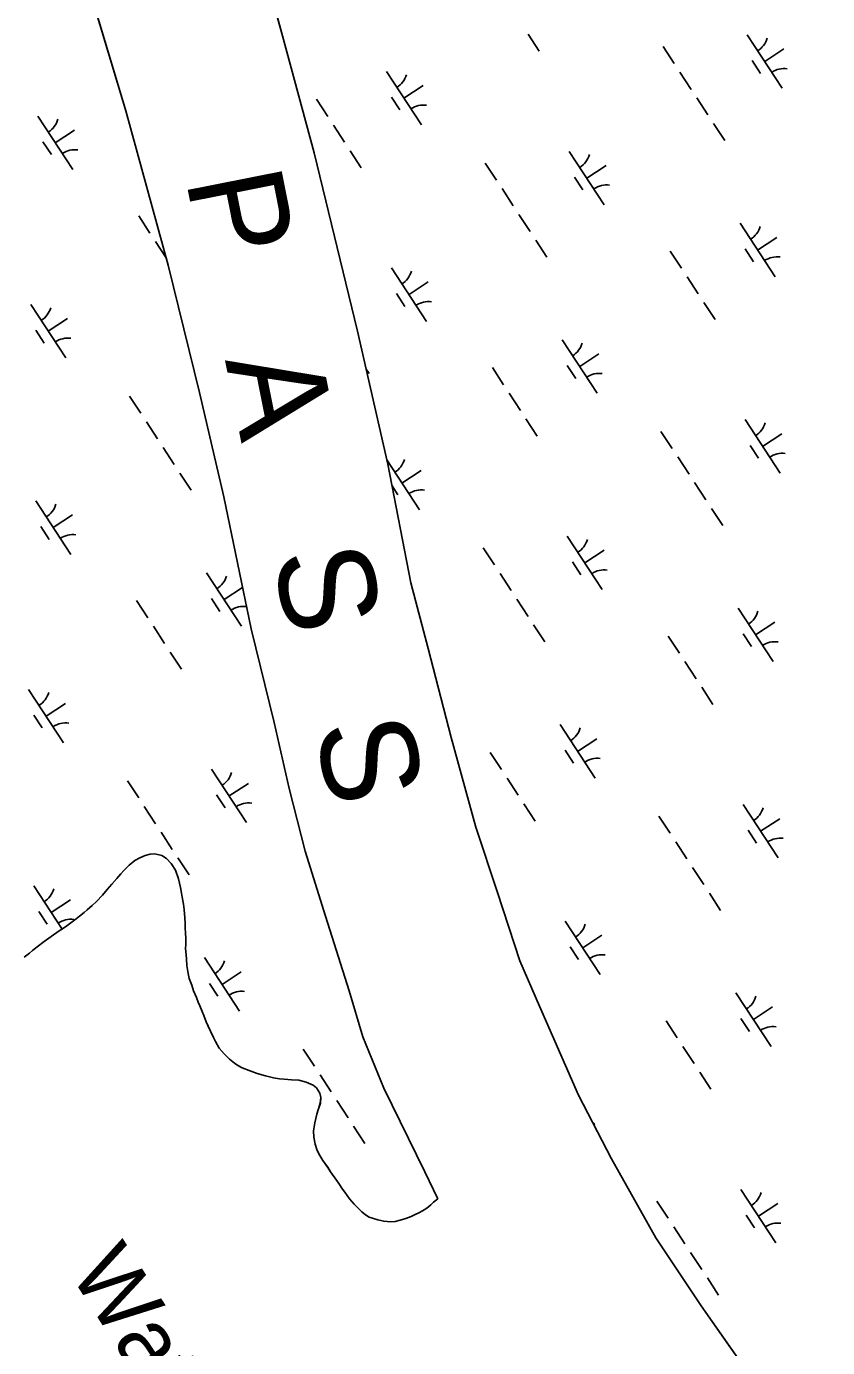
# Model space of a CAD drawing. Extents: x 3945642 to 3966284, y 206476 to 228921.
# Drawn here: x 3962719 to 3963346, y 213624 to 214658 of the extents above; entities that cross this region are included whole.
import ezdxf

# ---------------------------------------------------------------- set-up
doc = ezdxf.new("R2010")
doc.units = 0
for name, color, linetype in [('V-RIVR-IDEN', 7, 'Continuous'), ('V-TOPO-SHOR', 7, 'Continuous'), ('V-WETL-SWMP', 7, 'Continuous')]:
    doc.layers.add(name, color=color, linetype=linetype)

msp = doc.modelspace()

# ---------------------------------------------------------------- linework, layer by layer
at = {"layer": 'V-TOPO-SHOR'}
for points in [[(3962736.8, 215156.6), (3962773.4, 215081.9), (3962808.9, 215001.2), (3962834.9, 214934.8), (3962861.9, 214852.6), (3962884.9, 214776.1), (3962919.8, 214650.2), (3962944.5, 214558.8), (3962978.3, 214419.3), (3963002.1, 214315.1), (3963020.1, 214222.4), (3963033.6, 214171), (3963051.6, 214101.2), (3963070.9, 214031.3), (3963088, 213980), (3963105.5, 213926.7), (3963120.9, 213891.2), (3963151.2, 213821.4), (3963177.1, 213771.8), (3963211.9, 213710), (3963247.2, 213656.6), (3963292.5, 213592.3), (3963347.3, 213530.2)], [(3963041.3, 213740.5), (3963031.1, 213761.6), (3962999.1, 213827), (3962982.7, 213867.2), (3962971.8, 213903.2), (3962953.4, 213961.6), (3962937.5, 214012.5), (3962925, 214061.4), (3962913.2, 214113.1), (3962895.2, 214186.4), (3962873.9, 214289.6), (3962854.8, 214371.1), (3962830.3, 214470.9), (3962797.1, 214591.7), (3962767.6, 214690.2), (3962738.9, 214781.5), (3962714.1, 214844.4), (3962681.2, 214920), (3962656.7, 214977.6), (3962637, 215021), (3962616.5, 215070.2), (3962596.5, 215120.2)], [(3962717.6, 213929.4), (3962721.8, 213932.7), (3962724.2, 213934.8), (3962727.8, 213937.5), (3962733.3, 213941.7), (3962738.8, 213945.7), (3962745, 213950), (3962747.6, 213951.6), (3962751, 213954), (3962754.1, 213956.4), (3962758.4, 213959.5), (3962761, 213961.5), (3962764.5, 213964.5), (3962766.9, 213966.6), (3962770.7, 213969.9), (3962774.1, 213973.1), (3962778.8, 213977.9), (3962782.5, 213982.5), (3962786.2, 213986.7), (3962790.1, 213991.1), (3962793.3, 213994.6), (3962795.6, 213997.3), (3962799.8, 214001.4), (3962804.3, 214005), (3962808.2, 214007.2), (3962812.2, 214009), (3962816.3, 214010), (3962819.8, 214010.2), (3962825.3, 214009), (3962829.1, 214006.7), (3962832.7, 214002.8), (3962835.9, 213997.5), (3962838.4, 213990.8), (3962840, 213983.9), (3962840.8, 213979.6), (3962841.3, 213976.5), (3962842.2, 213970.9), (3962842.8, 213966.7), (3962843.4, 213960.2), (3962843.5, 213955.9), (3962843.6, 213952.8), (3962843.9, 213947.9), (3962844, 213944.5), (3962844.1, 213939.4), (3962843.9, 213936.2), (3962844.3, 213931.2), (3962844.5, 213927.9), (3962845, 213922.9), (3962845.5, 213919.7), (3962846, 213916.6), (3962846.8, 213912.7), (3962848.7, 213907.7), (3962850.2, 213903.1), (3962852.4, 213897.9), (3962853.8, 213894.3), (3962855, 213891.4), (3962857, 213886.9), (3962858.2, 213883.8), (3962860, 213879), (3962861.3, 213876), (3962863.3, 213871.6), (3962865.7, 213866.5), (3962867.3, 213863.4), (3962870.3, 213858.2), (3962874.2, 213853.8), (3962878.2, 213849.7), (3962882.2, 213846.6), (3962884.8, 213844.8), (3962888.2, 213842.9), (3962893.7, 213840.7), (3962900, 213838.5), (3962906.4, 213836.6), (3962912.8, 213835.2), (3962917.4, 213834.4), (3962920.9, 213834.1), (3962926.8, 213833.6), (3962932.6, 213833.2), (3962938.3, 213831.8), (3962943.7, 213829.3), (3962946.2, 213827.2), (3962949, 213823), (3962949.7, 213819.6), (3962949.3, 213815.2), (3962947.7, 213810.1), (3962946.6, 213806.7), (3962944.9, 213800), (3962943.9, 213793.6), (3962944.3, 213788.6), (3962945.2, 213783.3), (3962946.7, 213779.1), (3962948.1, 213775.7), (3962951.4, 213770.3), (3962955.1, 213765), (3962957.4, 213761.5), (3962962.1, 213755.1), (3962963.8, 213752.4), (3962966.7, 213748), (3962968.6, 213745.5), (3962972.1, 213740.3)], [(3962972.1, 213740.3), (3962975.7, 213736.3), (3962978.8, 213733), (3962981.9, 213730.2), (3962984.7, 213727.8), (3962987.6, 213726.1), (3962990.8, 213724.9), (3962994.2, 213723.9), (3962998.9, 213722.9), (3963004.1, 213722.5), (3963007.9, 213722.7), (3963011.8, 213723.8), (3963016.1, 213725), (3963020.5, 213726.7), (3963023.6, 213728.1), (3963026.5, 213729.5), (3963029.3, 213731), (3963032.7, 213733), (3963035.8, 213735.6), (3963037.9, 213737.8), (3963041.3, 213740.5)]]:
    msp.add_lwpolyline(points, dxfattribs=at)
at = {"layer": 'V-WETL-SWMP'}
for p, q in [((3962919.8, 214650.2), (3962884.9, 214776.1)), ((3962797.1, 214591.7), (3962767.6, 214690.2)), ((3962944.5, 214558.8), (3962919.8, 214650.2)), ((3963111.8, 214651.6), (3963120.6, 214638.2)), ((3963283.3, 214651), (3963310.7, 214609.2)), ((3963217.5, 214641.9), (3963226.2, 214628.5)), ((3963297, 214630.1), (3963312, 214640)), ((3963001, 214622.4), (3963028.4, 214580.6)), ((3963287.2, 214630.9), (3963293.8, 214620.9)), ((3963230.6, 214621.8), (3963239.4, 214608.4)), ((3963005, 214602.3), (3963011.6, 214592.3)), ((3963014.7, 214601.5), (3963029.8, 214611.4)), ((3963243.8, 214601.7), (3963252.5, 214588.4)), ((3962830.3, 214470.9), (3962797.1, 214591.7)), ((3962946.4, 214600.6), (3962955.1, 214587.2)), ((3962728.3, 214587.5), (3962755.7, 214545.7)), ((3963256.9, 214581.7), (3963265.7, 214568.3)), ((3962742, 214566.6), (3962757.1, 214576.4)), ((3962959.5, 214580.5), (3962968.3, 214567.1)), ((3962732.3, 214567.4), (3962738.9, 214557.3)), ((3962972.7, 214560.4), (3962981.4, 214547)), ((3963144.1, 214559.9), (3963171.5, 214518)), ((3962978.3, 214419.3), (3962944.5, 214558.8)), ((3963078.3, 214550.7), (3963087.1, 214537.4)), ((3963148.1, 214539.7), (3963154.7, 214529.7)), ((3963157.8, 214539), (3963172.9, 214548.8)), ((3963091.5, 214530.7), (3963100.2, 214517.3)), ((3962807.2, 214509.4), (3962816, 214496)), ((3963104.6, 214510.6), (3963113.4, 214497.2)), ((3963277.7, 214503.6), (3963305.1, 214461.8)), ((3962820.4, 214489.3), (3962828.7, 214476.6)), ((3963117.8, 214490.5), (3963126.5, 214477.1)), ((3963291.4, 214482.7), (3963306.5, 214492.6)), ((3963223, 214481.8), (3963231.8, 214468.4)), ((3963281.7, 214483.5), (3963288.2, 214473.5)), ((3962854.8, 214371.1), (3962830.3, 214470.9)), ((3963005, 214468.7), (3963032.4, 214426.9)), ((3963018.7, 214447.8), (3963033.7, 214457.7)), ((3963236.2, 214461.7), (3963244.9, 214448.3)), ((3963008.9, 214448.6), (3963015.5, 214438.6)), ((3962722.8, 214440.1), (3962750.2, 214398.3)), ((3963249.3, 214441.7), (3963258.1, 214428.3)), ((3962736.5, 214419.2), (3962751.5, 214429.1)), ((3962726.7, 214420), (3962733.3, 214409.9)), ((3963002.1, 214315.1), (3962978.3, 214419.3)), ((3963138.6, 214412.5), (3963166, 214370.7)), ((3963152.3, 214391.6), (3963167.3, 214401.4)), ((3962985.2, 214389.4), (3962987.4, 214386)), ((3963083.9, 214390.7), (3963092.6, 214377.3)), ((3963142.5, 214392.4), (3963149.1, 214382.3)), ((3962800, 214368.4), (3962808.8, 214355.1)), ((3962873.9, 214289.6), (3962854.8, 214371.1)), ((3963097, 214370.6), (3963105.8, 214357.2)), ((3962813.2, 214348.4), (3962822, 214335)), ((3963110.2, 214350.5), (3963118.9, 214337.1)), ((3963281.6, 214350), (3963309, 214308.1)), ((3963215.8, 214340.8), (3963224.6, 214327.4)), ((3963295.3, 214329), (3963310.4, 214338.9)), ((3962826.4, 214328.3), (3962835.1, 214314.9)), ((3963285.6, 214329.8), (3963292.2, 214319.8)), ((3963001.3, 214318.5), (3963026.8, 214279.5)), ((3963020.1, 214222.4), (3963002.1, 214315.1)), ((3963229, 214320.8), (3963237.8, 214307.4)), ((3962839.5, 214308.2), (3962848.3, 214294.8)), ((3963013.1, 214300.4), (3963028.2, 214310.3)), ((3963005.4, 214298.2), (3963010, 214291.2)), ((3963242.1, 214300.7), (3963250.9, 214287.3)), ((3962726.7, 214286.4), (3962754.1, 214244.6)), ((3962895.2, 214186.4), (3962873.9, 214289.6)), ((3962740.4, 214265.5), (3962755.5, 214275.4)), ((3963255.3, 214280.6), (3963264.1, 214267.2)), ((3962730.7, 214266.3), (3962737.2, 214256.3)), ((3963142.5, 214258.8), (3963169.9, 214217)), ((3963076.7, 214249.7), (3963085.5, 214236.3)), ((3963156.2, 214237.9), (3963171.3, 214247.8)), ((3962860.3, 214230.2), (3962887.7, 214188.4)), ((3963089.9, 214229.6), (3963098.6, 214216.2)), ((3963146.5, 214238.7), (3963153, 214228.6)), ((3962874, 214209.3), (3962888.5, 214218.8)), ((3963033.6, 214171), (3963020.1, 214222.4)), ((3962864.2, 214210.1), (3962870.8, 214200)), ((3963103, 214209.5), (3963111.8, 214196.1)), ((3962805.6, 214208.4), (3962814.4, 214195)), ((3963276.1, 214202.6), (3963303.5, 214160.7)), ((3962818.7, 214188.3), (3962827.5, 214174.9)), ((3963116.2, 214189.4), (3963124.9, 214176.1)), ((3963289.8, 214181.7), (3963304.8, 214191.5)), ((3962913.2, 214113.1), (3962895.2, 214186.4)), ((3963221.4, 214180.7), (3963230.2, 214167.4)), ((3963280, 214182.5), (3963286.6, 214172.4)), ((3962831.9, 214168.2), (3962840.7, 214154.8)), ((3963051.6, 214101.2), (3963033.6, 214171)), ((3963234.5, 214160.7), (3963243.3, 214147.3)), ((3962721.1, 214139), (3962748.5, 214097.2)), ((3963247.7, 214140.6), (3963256.5, 214127.2)), ((3962734.8, 214118.1), (3962749.9, 214128)), ((3962725.1, 214118.9), (3962731.7, 214108.9)), ((3962925, 214061.4), (3962913.2, 214113.1)), ((3963136.9, 214111.4), (3963164.3, 214069.6)), ((3963070.9, 214031.3), (3963051.6, 214101.2)), ((3963150.6, 214090.5), (3963165.7, 214100.4)), ((3963082.3, 214089.6), (3963091, 214076.2)), ((3963140.9, 214091.3), (3963147.5, 214081.3)), ((3962864.2, 214076.5), (3962891.6, 214034.7)), ((3962798.4, 214067.4), (3962807.2, 214054)), ((3962877.9, 214055.6), (3962893, 214065.4)), ((3963095.4, 214069.5), (3963104.2, 214056.1)), ((3962868.2, 214056.4), (3962874.8, 214046.3)), ((3962937.5, 214012.5), (3962925, 214061.4)), ((3962811.6, 214047.3), (3962820.3, 214033.9)), ((3963108.6, 214049.4), (3963117.3, 214036)), ((3963280, 214048.9), (3963307.4, 214007.1)), ((3963214.2, 214039.8), (3963223, 214026.4)), ((3963293.7, 214028), (3963308.8, 214037.8)), ((3962824.7, 214027.2), (3962833.5, 214013.8)), ((3963088, 213980), (3963070.9, 214031.3)), ((3963284, 214028.8), (3963290.6, 214018.7)), ((3962953.4, 213961.6), (3962937.5, 214012.5)), ((3963227.4, 214019.7), (3963236.1, 214006.3)), ((3962799.8, 214001.4), (3962804.3, 214005)), ((3962804.3, 214005), (3962808.2, 214007.2)), ((3962808.2, 214007.2), (3962812.2, 214009)), ((3962812.2, 214009), (3962816.3, 214010)), ((3962816.3, 214010), (3962819.8, 214010.2)), ((3962819.8, 214010.2), (3962825.3, 214009)), ((3962825.3, 214009), (3962829.1, 214006.7)), ((3962829.1, 214006.7), (3962832.7, 214002.8)), ((3962832.7, 214002.8), (3962835.9, 213997.5)), ((3962837.9, 214007.1), (3962846.7, 213993.8)), ((3962790.1, 213991.1), (3962793.3, 213994.6)), ((3962793.3, 213994.6), (3962795.6, 213997.3)), ((3962795.6, 213997.3), (3962799.8, 214001.4)), ((3962835.9, 213997.5), (3962838.4, 213990.8)), ((3963240.5, 213999.6), (3963249.3, 213986.2)), ((3962725.1, 213985.3), (3962747.3, 213951.4)), ((3962778.8, 213977.9), (3962782.5, 213982.5)), ((3962782.5, 213982.5), (3962786.2, 213986.7)), ((3962786.2, 213986.7), (3962790.1, 213991.1)), ((3962838.4, 213990.8), (3962840, 213983.9)), ((3962840, 213983.9), (3962840.8, 213979.6)), ((3962738.8, 213964.4), (3962753.8, 213974.3)), ((3962770.7, 213969.9), (3962774.1, 213973.1)), ((3962774.1, 213973.1), (3962778.8, 213977.9)), ((3962840.8, 213979.6), (3962841.3, 213976.5)), ((3962841.3, 213976.5), (3962842.2, 213970.9)), ((3962842.2, 213970.9), (3962842.8, 213966.7)), ((3963105.5, 213926.7), (3963088, 213980)), ((3963253.7, 213979.5), (3963262.4, 213966.1)), ((3962729, 213965.2), (3962735.6, 213955.2)), ((3962758.4, 213959.5), (3962761, 213961.5)), ((3962761, 213961.5), (3962764.5, 213964.5)), ((3962764.5, 213964.5), (3962766.9, 213966.6)), ((3962766.9, 213966.6), (3962770.7, 213969.9)), ((3962842.8, 213966.7), (3962843.4, 213960.2)), ((3962971.8, 213903.2), (3962953.4, 213961.6)), ((3962745, 213950), (3962747.6, 213951.6)), ((3962747.6, 213951.6), (3962751, 213954)), ((3962751, 213954), (3962754.1, 213956.4)), ((3962754.1, 213956.4), (3962758.4, 213959.5)), ((3962843.4, 213960.2), (3962843.5, 213955.9)), ((3962843.5, 213955.9), (3962843.6, 213952.8)), ((3962843.6, 213952.8), (3962843.9, 213947.9)), ((3963140.9, 213957.7), (3963168.3, 213915.9)), ((3962727.8, 213937.5), (3962733.3, 213941.7)), ((3962733.3, 213941.7), (3962738.8, 213945.7)), ((3962738.8, 213945.7), (3962745, 213950)), ((3962843.9, 213947.9), (3962844, 213944.5)), ((3962844, 213944.5), (3962844.1, 213939.4)), ((3963154.6, 213936.8), (3963169.6, 213946.7)), ((3962717.6, 213929.4), (3962721.8, 213932.7)), ((3962721.8, 213932.7), (3962724.2, 213934.8)), ((3962724.2, 213934.8), (3962727.8, 213937.5)), ((3962844.1, 213939.4), (3962843.9, 213936.2)), ((3962843.9, 213936.2), (3962844.3, 213931.2)), ((3962844.3, 213931.2), (3962844.5, 213927.9)), ((3963144.8, 213937.6), (3963151.4, 213927.6)), ((3962844.5, 213927.9), (3962845, 213922.9)), ((3962845, 213922.9), (3962845.5, 213919.7)), ((3962845.5, 213919.7), (3962846, 213916.6)), ((3962858.7, 213929.1), (3962886.1, 213887.3)), ((3963120.9, 213891.2), (3963105.5, 213926.7)), ((3962846, 213916.6), (3962846.8, 213912.7)), ((3962846.8, 213912.7), (3962848.7, 213907.7)), ((3962862.6, 213909), (3962869.2, 213899)), ((3962872.4, 213908.2), (3962887.4, 213918.1)), ((3962848.7, 213907.7), (3962850.2, 213903.1)), ((3962850.2, 213903.1), (3962852.4, 213897.9)), ((3962982.7, 213867.2), (3962971.8, 213903.2)), ((3963274.5, 213901.5), (3963301.9, 213859.7)), ((3962852.4, 213897.9), (3962853.8, 213894.3)), ((3962853.8, 213894.3), (3962855, 213891.4)), ((3962855, 213891.4), (3962857, 213886.9)), ((3963151.2, 213821.4), (3963120.9, 213891.2)), ((3963288.2, 213880.6), (3963303.2, 213890.5)), ((3962857, 213886.9), (3962858.2, 213883.8)), ((3962858.2, 213883.8), (3962860, 213879)), ((3962860, 213879), (3962863.3, 213871.6)), ((3963219.8, 213879.7), (3963228.5, 213866.3)), ((3963278.4, 213881.4), (3963285, 213871.3)), ((3962863.3, 213871.6), (3962865.7, 213866.5)), ((3962865.7, 213866.5), (3962867.3, 213863.4)), ((3962867.3, 213863.4), (3962870.3, 213858.2)), ((3962870.3, 213858.2), (3962874.2, 213853.8)), ((3962935.9, 213857.5), (3962944.7, 213844.1)), ((3962999.1, 213827), (3962982.7, 213867.2)), ((3963232.9, 213859.6), (3963241.7, 213846.2)), ((3962874.2, 213853.8), (3962878.2, 213849.7)), ((3962878.2, 213849.7), (3962882.2, 213846.6)), ((3962882.2, 213846.6), (3962884.8, 213844.8)), ((3962884.8, 213844.8), (3962888.2, 213842.9)), ((3962888.2, 213842.9), (3962893.7, 213840.7)), ((3962893.7, 213840.7), (3962900, 213838.5)), ((3962900, 213838.5), (3962906.4, 213836.6)), ((3962906.4, 213836.6), (3962912.8, 213835.2)), ((3962949.1, 213837.4), (3962957.9, 213824)), ((3963246.1, 213839.5), (3963254.8, 213826.1)), ((3962912.8, 213835.2), (3962917.4, 213834.4)), ((3962917.4, 213834.4), (3962920.9, 213834.1)), ((3962920.9, 213834.1), (3962926.8, 213833.6)), ((3962926.8, 213833.6), (3962932.6, 213833.2)), ((3962932.6, 213833.2), (3962938.3, 213831.8)), ((3962938.3, 213831.8), (3962943.7, 213829.3)), ((3962943.7, 213829.3), (3962946.2, 213827.2)), ((3962946.2, 213827.2), (3962949, 213823)), ((3963031.1, 213761.6), (3962999.1, 213827)), ((3962949, 213823), (3962949.7, 213819.6)), ((3962949.7, 213819.6), (3962949.4, 213815.2)), ((3962962.3, 213817.3), (3962971, 213803.9)), ((3963177.1, 213771.8), (3963151.2, 213821.4)), ((3962946.6, 213806.7), (3962944.9, 213800)), ((3962947.7, 213810.1), (3962946.6, 213806.7)), ((3962949.4, 213815.2), (3962947.7, 213810.1)), ((3962944.9, 213800), (3962943.9, 213793.6)), ((3962975.4, 213797.2), (3962984.2, 213783.8)), ((3963163.1, 213798.6), (3963164.1, 213799.3)), ((3962943.9, 213793.6), (3962944.3, 213788.6)), ((3962944.3, 213788.6), (3962945.2, 213783.3)), ((3962945.2, 213783.3), (3962946.7, 213779.1)), ((3962946.7, 213779.1), (3962948.1, 213775.7)), ((3962948.1, 213775.7), (3962951.4, 213770.3)), ((3962951.4, 213770.3), (3962955.1, 213765.1)), ((3962955.1, 213765.1), (3962957.4, 213761.5)), ((3963211.9, 213710), (3963177.1, 213771.8)), ((3962957.4, 213761.5), (3962962.1, 213755.1)), ((3962962.1, 213755.1), (3962963.8, 213752.4)), ((3963041.3, 213740.5), (3963031.1, 213761.6)), ((3962963.8, 213752.4), (3962966.7, 213748)), ((3962966.7, 213748), (3962968.6, 213745.5)), ((3962968.6, 213745.5), (3962972.1, 213740.3)), ((3963278.4, 213747.8), (3963305.8, 213706)), ((3962972.1, 213740.3), (3962975.7, 213736.3)), ((3962975.7, 213736.3), (3962978.8, 213733)), ((3962978.8, 213733), (3962981.9, 213730.2)), ((3963029.3, 213731), (3963032.7, 213733)), ((3963032.7, 213733), (3963035.8, 213735.6)), ((3963035.8, 213735.6), (3963037.9, 213737.8)), ((3963037.9, 213737.8), (3963041.3, 213740.5)), ((3963212.6, 213738.7), (3963221.4, 213725.3)), ((3963292.1, 213726.9), (3963307.2, 213736.8)), ((3962981.9, 213730.2), (3962984.7, 213727.8)), ((3962984.7, 213727.8), (3962987.6, 213726.1)), ((3962987.6, 213726.1), (3962990.8, 213724.9)), ((3962990.8, 213724.9), (3962994.2, 213723.9)), ((3962994.2, 213723.9), (3962998.9, 213722.9)), ((3962998.9, 213722.9), (3963004.1, 213722.5)), ((3963004.1, 213722.5), (3963007.9, 213722.7)), ((3963007.9, 213722.7), (3963011.8, 213723.8)), ((3963011.8, 213723.8), (3963016.1, 213725)), ((3963016.1, 213725), (3963020.5, 213726.7)), ((3963020.5, 213726.7), (3963023.6, 213728.1)), ((3963023.6, 213728.1), (3963026.5, 213729.5)), ((3963026.5, 213729.5), (3963029.3, 213731)), ((3963282.4, 213727.7), (3963288.9, 213717.7)), ((3963225.8, 213718.6), (3963234.5, 213705.2)), ((3963247.2, 213656.6), (3963211.9, 213710)), ((3963238.9, 213698.5), (3963247.7, 213685.2)), ((3963252.1, 213678.5), (3963260.8, 213665.1)), ((3963292.5, 213592.3), (3963247.2, 213656.6))]:
    msp.add_line(p, q, dxfattribs=at)
for centre, start, end in [((3963282, 214653.3), 302.4575, 344.0011), ((3963312.3, 214607.1), 82.4574, 124.0011), ((3962999.8, 214624.7), 302.4575, 344.0011), ((3963030.1, 214578.5), 82.4574, 124.0011), ((3962727.1, 214589.8), 302.4575, 344.0011), ((3962757.4, 214543.6), 82.4574, 124.0011), ((3963142.9, 214562.2), 302.4575, 344.0011), ((3963173.2, 214516), 82.4574, 124.0011), ((3963276.5, 214506), 302.4575, 344.0011), ((3963306.7, 214459.8), 82.4574, 124.0011), ((3963003.7, 214471), 302.4575, 344.0011), ((3962721.5, 214442.4), 302.4575, 344.0011), ((3963034, 214424.8), 82.4574, 124.0011), ((3962751.8, 214396.2), 82.4574, 124.0011), ((3963137.3, 214414.8), 302.4575, 344.0011), ((3963167.6, 214368.6), 82.4574, 124.0011), ((3963280.4, 214352.3), 302.4575, 344.0011), ((3963310.7, 214306.1), 82.4574, 124.0011), ((3962998.2, 214323.7), 302.4575, 344.0011), ((3963028.5, 214277.5), 82.4574, 124.0011), ((3962725.5, 214288.7), 302.4575, 344.0011), ((3962755.7, 214242.5), 82.4574, 124.0011), ((3963141.3, 214261.1), 302.4575, 344.0011), ((3963171.5, 214214.9), 82.4574, 124.0011), ((3962859, 214232.5), 302.4575, 344.0011), ((3962889.3, 214186.3), 82.5422, 124.0011), ((3963274.8, 214204.9), 302.4575, 344.0011), ((3963305.1, 214158.7), 82.4574, 124.0011), ((3962719.9, 214141.4), 302.4575, 344.0011), ((3962750.2, 214095.2), 82.4574, 124.0011), ((3963135.7, 214113.7), 302.4575, 344.0011), ((3963166, 214067.5), 82.4574, 124.0011), ((3962863, 214078.8), 302.4575, 344.0011), ((3962893.3, 214032.6), 82.4574, 124.0011), ((3963278.8, 214051.2), 302.4575, 344.0011), ((3963309.1, 214005), 82.4574, 124.0011), ((3962723.8, 213987.7), 302.4575, 344.0011), ((3962754.1, 213941.5), 82.4574, 124.0011), ((3963139.6, 213960.1), 302.4575, 344.0011), ((3963169.9, 213913.8), 82.4574, 124.0011), ((3962857.4, 213931.4), 302.4575, 344.0011), ((3962887.7, 213885.2), 82.4574, 124.0011), ((3963273.2, 213903.8), 302.4575, 344.0011), ((3963303.5, 213857.6), 82.4574, 124.0011), ((3963277.2, 213750.1), 302.4575, 344.0011), ((3963307.4, 213703.9), 82.4574, 124.0011)]:
    msp.add_arc(centre, 17.6, start, end, dxfattribs=at)

# ---------------------------------------------------------------- texts
at = {"layer": 'V-RIVR-IDEN'}
for s, height, rotation, p in [('P', 75, 281.208, (3962844, 214537.8)), ('A', 75, 281.208, (3962874.7, 214396.6)), ('S', 75, 281.208, (3962911.8, 214244.2)), ('S', 75, 281.208, (3962944.7, 214110)), ('Water', 50, 302.6757, (3962752.3, 213683))]:
    msp.add_text(s, height=height, rotation=rotation, dxfattribs=at).set_placement(p)

doc.saveas('drawing.dxf')
